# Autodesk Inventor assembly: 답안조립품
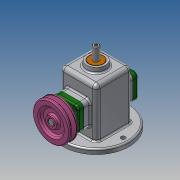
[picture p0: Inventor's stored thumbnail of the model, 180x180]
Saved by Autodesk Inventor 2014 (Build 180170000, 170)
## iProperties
Created: 2021-08
Part Number: 답안조립품
Document SubType Name: Weldment
Designer: kb542-04
Weld Material: Welded Aluminum-6061
Author: kb542-04
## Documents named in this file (16)
- C:\Users\kb542-04\Desktop\710806V1008\답안조립품.iam
- C:\Users\kb542-04\Desktop\710806V1008\본체.ipt
- C:\Users\kb542-04\Desktop\710806V1008\V벨트풀리.ipt
- C:\Users\kb542-04\Desktop\710806V1008\키 4x4x10.ipt
- C:\Users\kb542-04\Desktop\710806V1008\편심축.ipt
- C:\Users\kb542-04\Desktop\710806V1008\베어링 12x32x10.ipt
- C:\Users\kb542-04\Desktop\710806V1008\앞커버.ipt
- C:\Users\kb542-04\Desktop\710806V1008\오일 실 12 25 7.ipt
- C:\Users\kb542-04\Desktop\710806V1008\뒤커버.ipt
- C:\Users\kb542-04\Desktop\710806V1008\링크.ipt
- C:\Users\kb542-04\Desktop\710806V1008\슬라이드.ipt
- C:\Users\kb542-04\Desktop\710806V1008\고정핀 1.2x8.ipt
- C:\Users\kb542-04\Desktop\710806V1008\핀 5x18.ipt
- C:\Users\kb542-04\Desktop\710806V1008\부시.ipt
- C:\Users\kb542-04\Desktop\710806V1008\볼트 M4.ipt
- C:\Users\kb542-04\Desktop\710806V1008\멈춤나사 M3x8.ipt
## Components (3 placed, 3 different names)
1. V벨트풀리:1 — 플러쉬:1
2. 고정핀 1.2x8:1
3. 핀 5x18:1
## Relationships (1: Flush 1)
- 플러쉬:1 [Flush]: V벨트풀리:1
